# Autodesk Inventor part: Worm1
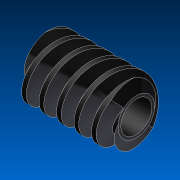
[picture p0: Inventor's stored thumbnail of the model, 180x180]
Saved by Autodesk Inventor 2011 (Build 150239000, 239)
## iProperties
Created: 2011-05
Part Number: Worm1
Material: Steel, Mild
Document SubType Name: Modeling
Designer: 904Chiaki
Categories: <?xml version="1.0" encoding="UTF-16"?> <MemberInstance><Categories><FamilyTemplate><FamilyTemplateParameter ValueType="xs:double" Id="1" ObjectReferenceKey="da
Density: 7.86 g/cm^3
Author: 904Chiaki
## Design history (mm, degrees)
sketch "Sketch6"
  geometry: C1 r 25 at (0, 0); A1 r 29.7 centre (0, 0) between (-21.876, -20.088) and (-3.871, -29.447) reference
  constraints: 1 centre point, 1 coincident
  dimensions: "d81" = 50 diameter of C1
extrude "Extrusion2" cut sketch "Sketch6" stored distance "d82" = 10; taper "d83" = 0 deg
workplane "Work Plane10"
pattern_circular "Left Tooth Pattern" dims angle "d73" = 360 deg, "da_rightdir" = 0 [user parameter]
pattern_circular "Tooth Pattern" dims angle "d46" = 360 deg, "da_rightdir" = 0 [user parameter]
sketch "Sketch5"
  geometry: C1 r 49.5 at (0, 0) reference; C2 r 40.5 at (0, 0)
  constraints: 1 centre point, 1 coincident
  dimensions: "d59" = 81 diameter of C2 (= da_d)
feature "Pitch Diameter" dims "d60" = 10, "d61" = 0
body "Srf1"
sketch "Tooth Sketch"
  geometry: L1 (0, 54.054)-(0, 25.641) reference; L2 (-109.485, 49.995)-(-102.098, 29.7); L3 (-95.822, 29.7)-(-88.436, 49.995); L4 (-113.694, 0)-(-84.226, 0) reference; L5 (-109.485, 49.995)-(-98.96, 49.995); L6 (-98.96, 49.995)-(-88.436, 49.995); L7 (-102.098, 29.7)-(-98.96, 29.7); L8 (-98.96, 29.7)-(-95.822, 29.7); L9 (-98.96, 40.5)-(-91.892, 40.5); L10 (-98.96, 49.995)-(-98.96, 29.7)
  constraints: 16 end point, 3 equal length, 3 parallel, 2 collinear, 2 point on line
  dimensions: "d24" = 110 deg angle of L7 L2 (computed from da_alfat); "d25" = 98.96017 distance from line of L1 L5.end (= fd_dist); "d26" = 7.06858 distance of L9.start L9.end (= 0.25 x da_px); "d27" = 29.7 distance between parallel lines of L4 L7 (= 0.5 x da_df); "d28" = 40.5 distance between parallel lines of L4 L9 (= 0.5 x da_d); "d29" = 49.995 distance between parallel lines of L4 L5 (= 0.505 x da_da)
feature "Left Tooth" sketch "Tooth Sketch" pitch "d62" = 56.54867 (computed from da_px, da_z); turns "d64" = 8 (= fd_n); dims "d63" = 10, "d65" = 0, angle "d66" = 90 deg, angle "d67" = 90 deg, "d68" = 0, "d69" = 0, "d76" = 10, "da_rightdir" = 0 [user parameter]
node "Base Body Sketch" dims "d5" = 99 (= da_da)
extrude "Base Body" new body stored distance "d6" = 150 (= da_b); taper "d7" = 0 deg
chamfer "Chamfer1" distance "d8" = 7.20661 (= fd_cham1); stored, may be unused: second distance "d9" = 19.8 (= 0.5 x fd_cham2), angle "d47" = 45 deg
chamfer "Chamfer2" distance "d10" = 7.20661 (= fd_cham1); stored, may be unused: second distance "d11" = 19.8 (= 0.5 x fd_cham2), angle "d48" = 45 deg
feature "Tooth" pitch "d30" = 56.54867 (computed from da_px, da_z); turns "d32" = 8 (= fd_n); dims "d31" = 10, "d33" = 0, angle "d34" = 90 deg, angle "d35" = 90 deg, "d36" = 0, "d37" = 0, "d70" = 10, "da_rightdir" = 0 [user parameter]
body "Solid1"
other parameters: "da_aw" = 238.5 [user parameter; used in 2 equation terms], "da_b" = 150 [user parameter; used in 3 equation terms], "da_df" = 59.4 [user parameter; used in 2 equation terms], "da_da" = 99 [user parameter; used in 3 equation terms], "fd_cham2" = 39.6 (= da_da - da_df) [user parameter; used in 3 equation terms], "fd_cham1" = 7.20661 (= 0.181985 x fd_cham2) [user parameter; used in 2 equation terms], "da_d" = 81 [user parameter; used in 2 equation terms], "da_px" = 162 deg [user parameter; used in 5 equation terms], "fd_dist" = 98.96017 (computed from da_b, da_px) [user parameter; used in 1 equation term], "fd_n" = 8 (computed from da_b, da_px) [user parameter; used in 2 equation terms], "da_alfat" = 20 deg [user parameter; used in 1 equation term], "d12" = 110 deg (derived), "d14" = 3.1425 (derived), "d49" = 238.5 (= da_aw), "d50" = 0, "d54" = 0, "d56" = 0, "d77" = 0, "d79" = 238.5 (= da_aw), "d80" = 0, "d84" = -75
